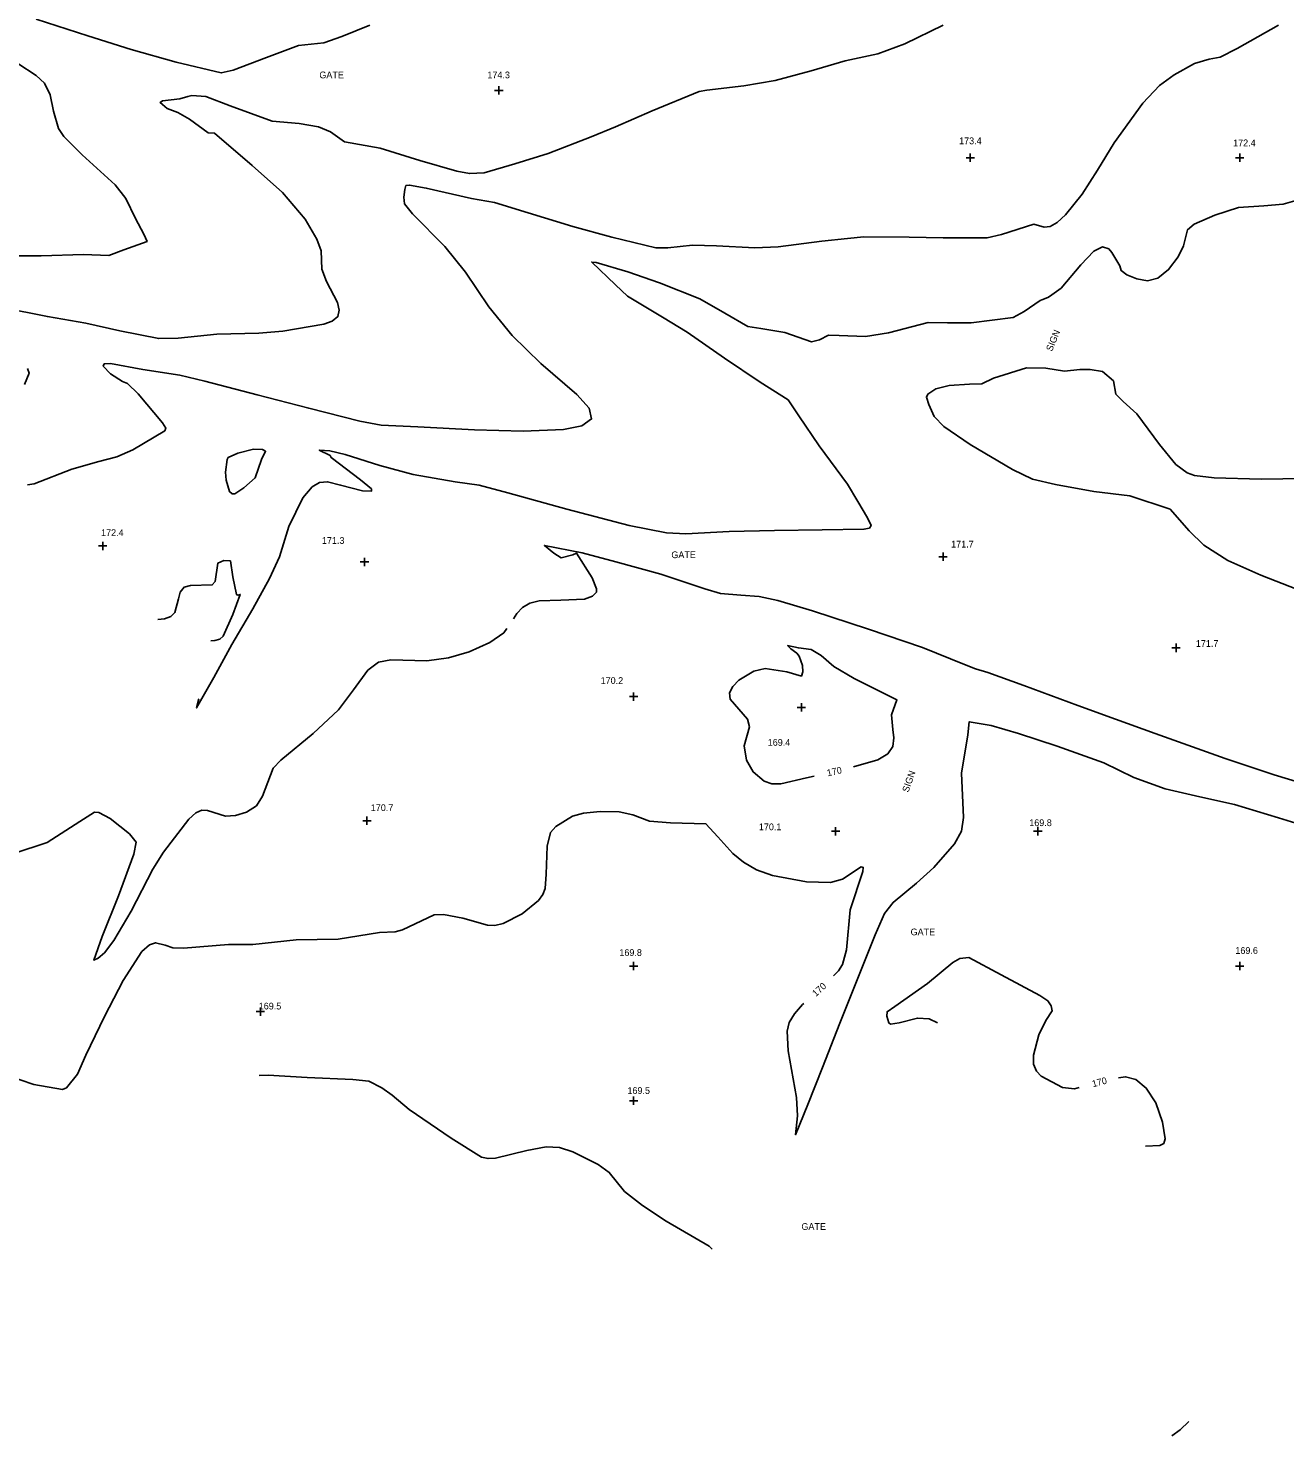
# Model space of a CAD drawing. Extents: x 1467615 to 2003689, y 770235 to 1108726.
# Drawn here: x 1997360.2 to 1997733.4, y 775740.5 to 776158.5 of the extents above; entities that cross this region are included whole.
import ezdxf

# ---------------------------------------------------------------- set-up
doc = ezdxf.new("R2010")
doc.units = 0
for name, color, linetype in [('RD_DTM_Major1', 7, 'Continuous'), ('RD_DTM_Major1_Lbl', 7, 'Continuous'), ('RD_DTM_Minor1', 7, 'Continuous'), ('RD_DTM_Spot_Elev', 7, 'Continuous'), ('RD_TX_Misc1', 7, 'Continuous')]:
    doc.layers.add(name, color=color, linetype=linetype)

msp = doc.modelspace()

# ---------------------------------------------------------------- linework, layer by layer
at = {"layer": 'RD_DTM_Major1'}
for points in [[(1997362.62, 776161.17), (1997377.91, 776156.18), (1997390.79, 776152.18), (1997404.2, 776148.39), (1997417.56, 776145.17), (1997421.12, 776145.99), (1997430.95, 776149.74), (1997440.52, 776153.37), (1997448.02, 776154.07), (1997453.38, 776156.03), (1997461.66, 776159.38)], [(1997353.3, 776090.9), (1997364.12, 776090.83), (1997376.68, 776091.32), (1997384.18, 776090.99), (1997388.61, 776092.65), (1997395.53, 776095.16), (1997394.57, 776097.26), (1997392.1, 776101.92), (1997389.19, 776107.94), (1997386.05, 776111.96), (1997376.28, 776120.86), (1997370.78, 776126.3), (1997369.26, 776128.66), (1997367.71, 776133.87), (1997366.8, 776138.72), (1997365.07, 776142.18), (1997362.63, 776144.4), (1997357.11, 776147.96)], [(1997593.58, 775936.4), (1997591.32, 775935.88), (1997583.69, 775934.06), (1997581.08, 775934.13), (1997578.83, 775934.88), (1997575.54, 775937.63), (1997573.53, 775941.12), (1997572.82, 775945.38), (1997574.42, 775951.03), (1997573.86, 775953.31), (1997568.64, 775959.22), (1997568.5, 775961.08), (1997569.47, 775963.02), (1997571.28, 775964.87), (1997575.7, 775967.6), (1997579.06, 775968.3), (1997585.51, 775967.39), (1997589.85, 775966.09), (1997590.28, 775967.34), (1997590.15, 775969.23), (1997589.22, 775972), (1997588.48, 775972.93), (1997586.68, 775974.18), (1997585.72, 775975.13), (1997588.96, 775974.48), (1997592.74, 775974), (1997595.73, 775972.18), (1997599.48, 775968.98), (1997605.46, 775965.37), (1997618.2, 775959.06), (1997616.62, 775954.58), (1997616.95, 775950.25), (1997617.26, 775947.72), (1997616.97, 775945.23), (1997615.51, 775943.02), (1997612.55, 775941.25), (1997605.26, 775939.13)], [(1997590.53, 775868.89), (1997590.2, 775868.59), (1997587.74, 775865.82), (1997586.23, 775863.2), (1997585.57, 775860.62), (1997585.91, 775854.82), (1997588.35, 775840.98), (1997588.68, 775835.52), (1997588.06, 775829.89), (1997591.7, 775838.88), (1997596.07, 775849.84), (1997601.29, 775862.99), (1997606.42, 775875.88), (1997611.77, 775889.27), (1997614.52, 775895.59), (1997617.07, 775898.9), (1997623.97, 775904.63), (1997629.15, 775909.23), (1997635.3, 775916.29), (1997637.41, 775920.02), (1997638.01, 775924.1), (1997637.35, 775937.22), (1997639.24, 775948.66), (1997639.66, 775952.55), (1997646.19, 775951.38), (1997654.31, 775949.08), (1997665.78, 775945.25), (1997679.64, 775940.34), (1997688.57, 775935.95), (1997697.88, 775932.65), (1997708.19, 775930.28), (1997718.47, 775927.95), (1997731.47, 775924.04), (1997744.41, 775920.04)], [(1997349.64, 775848.99), (1997361.89, 775844.86), (1997370.44, 775843.36), (1997371.56, 775843.85), (1997374.88, 775847.85), (1997377.33, 775853.55), (1997382.86, 775864.98), (1997388.45, 775875.71), (1997394, 775884.3), (1997396.24, 775886.31), (1997398.07, 775886.94), (1997400.87, 775886.16), (1997403.17, 775885.39), (1997406.4, 775885.33), (1997419.69, 775886.38), (1997426.92, 775886.42), (1997439.79, 775887.76), (1997452.26, 775887.97), (1997464.58, 775889.93), (1997469.18, 775890.2), (1997471.43, 775890.77), (1997480.76, 775895.23), (1997483.55, 775895.35), (1997489.34, 775894.17), (1997496.59, 775892.11), (1997498.82, 775892.07), (1997501.28, 775892.61), (1997506.96, 775895.5), (1997511.74, 775899.42), (1997513.07, 775901.25), (1997513.75, 775903.04), (1997514.03, 775907.25), (1997514.3, 775915.62), (1997515.3, 775919.64), (1997516.91, 775921.48), (1997521.84, 775924.52), (1997525.11, 775925.38), (1997530.06, 775925.87), (1997535.71, 775925.75), (1997539.77, 775924.85), (1997544.76, 775922.99), (1997550.96, 775922.48), (1997561.46, 775922.26), (1997565.05, 775918.39), (1997569.46, 775913.43), (1997572.6, 775910.83), (1997576.54, 775908.55), (1997581.3, 775906.85), (1997591.36, 775905.04), (1997598.49, 775904.8), (1997602.02, 775905.76), (1997607.56, 775909.44), (1997608.2, 775909.28), (1997608.1, 775908.12), (1997604.36, 775896.68), (1997603.25, 775884.8), (1997602.09, 775880.44), (1997600.89, 775878.57), (1997599.33, 775877.05)], [(1997672.36, 775843.94), (1997670.89, 775843.55), (1997667.41, 775843.9), (1997661.08, 775847.31), (1997659.61, 775848.78), (1997658.75, 775850.83), (1997658.72, 775853.54), (1997660.34, 775859.57), (1997662.39, 775863.79), (1997664.26, 775866.75), (1997664, 775868.19), (1997663, 775869.63), (1997660.63, 775871.3), (1997649.2, 775877.43), (1997639.6, 775882.52), (1997636.91, 775882.25), (1997634.76, 775881.02), (1997627.27, 775874.85), (1997617.55, 775868.02), (1997615.26, 775866.42), (1997615.16, 775865.1), (1997615.81, 775863.09), (1997616.31, 775862.75), (1997618.85, 775863.15), (1997624.3, 775864.55), (1997627.8, 775864.31), (1997630.28, 775863.12)], [(1997692.02, 775826.51), (1997696.3, 775826.7), (1997697.44, 775827.35), (1997697.83, 775828.69), (1997697.11, 775833.62), (1997695.04, 775839.43), (1997692.24, 775843.77), (1997689.19, 775846.28), (1997686.08, 775847.13), (1997684.01, 775846.82)]]:
    msp.add_lwpolyline(points, dxfattribs=at)
at = {"layer": 'RD_DTM_Minor1'}
for points in [[(1997352.52, 776075.58), (1997365.95, 776072.85), (1997377.37, 776070.85), (1997387.46, 776068.6), (1997399, 776066.3), (1997404.79, 776066.39), (1997416.23, 776067.66), (1997428.77, 776067.94), (1997435.82, 776068.5), (1997448.01, 776070.62), (1997450.54, 776071.48), (1997452.19, 776072.83), (1997452.62, 776074.74), (1997452.1, 776077.02), (1997448.83, 776083.24), (1997447.39, 776086.88), (1997447.2, 776092.37), (1997445.91, 776095.87), (1997442.46, 776101.79), (1997435.75, 776109.67), (1997426.7, 776117.66), (1997415.54, 776127.27), (1997413.66, 776127.42), (1997408.1, 776131.45), (1997404.63, 776133.39), (1997401.49, 776134.61), (1997399.39, 776136.37), (1997400.07, 776136.88), (1997405.23, 776137.51), (1997407.66, 776138.16), (1997408.86, 776138.44), (1997412.99, 776138.17), (1997420.18, 776135.46), (1997432.66, 776130.9), (1997440.65, 776130.13), (1997446.47, 776129.2), (1997450.05, 776127.74), (1997454.18, 776124.73), (1997464.8, 776122.8), (1997476.57, 776119.16), (1997487.53, 776116.04), (1997491.27, 776115.28), (1997495.59, 776115.49), (1997504.75, 776118.17), (1997514.66, 776121.28), (1997527.44, 776126.17), (1997534.6, 776129.22), (1997545.48, 776133.97), (1997559.47, 776139.62), (1997561.79, 776140.08), (1997572.74, 776141.34), (1997582.03, 776142.91), (1997592.72, 776145.76), (1997602.81, 776148.76), (1997612.56, 776150.88), (1997620.6, 776153.8), (1997631.89, 776159.33)], [(1997360.01, 776022.91), (1997362.01, 776023.17), (1997373.19, 776027.57), (1997381.21, 776029.76), (1997386.57, 776031.2), (1997391.28, 776033.26), (1997400.85, 776038.96), (1997401.14, 776039.74), (1997400.07, 776041.27), (1997392.9, 776049.89), (1997389.7, 776052.99), (1997388.21, 776053.53), (1997384.72, 776055.88), (1997382.51, 776058.16), (1997382.83, 776058.82), (1997384.63, 776058.87), (1997394.25, 776057.15), (1997405.22, 776055.42), (1997412.67, 776053.64), (1997428.18, 776049.65), (1997443.55, 776045.6), (1997458.74, 776041.77), (1997465.07, 776040.62), (1997475.93, 776040.06), (1997492.77, 776039.18), (1997507.19, 776038.86), (1997519.18, 776039.34), (1997524.62, 776040.4), (1997527.53, 776042.43), (1997526.78, 776045.63), (1997523.18, 776049.73), (1997512.49, 776058.95), (1997503.92, 776067.26), (1997497.05, 776075.77), (1997490.13, 776086.07), (1997484, 776093.61), (1997474.4, 776103.31), (1997472, 776106.35), (1997471.77, 776108.33), (1997472.12, 776110.55), (1997472.39, 776111.72), (1997473.51, 776111.86), (1997478.45, 776110.98), (1997491.84, 776107.91), (1997498.74, 776106.74), (1997508.73, 776103.66), (1997521.92, 776099.63), (1997533.51, 776096.37), (1997546.62, 776093.29), (1997550.18, 776093.21), (1997557.53, 776094), (1997564.58, 776093.87), (1997576.01, 776093.27), (1997582.96, 776093.51), (1997595.88, 776095.23), (1997603.48, 776096), (1997608.42, 776096.49), (1997621.86, 776096.43), (1997631.96, 776096.25), (1997644.97, 776096.24), (1997649.27, 776097.2), (1997658.84, 776100.25), (1997661.91, 776099.34), (1997663.68, 776099.63), (1997665.81, 776100.79), (1997668.26, 776103.02), (1997673.19, 776109.14), (1997677.74, 776116.28), (1997682.75, 776124.47), (1997691.25, 776136.25), (1997696.19, 776141.43), (1997700.49, 776144.64), (1997706.55, 776147.95), (1997710.93, 776149.23), (1997714.17, 776149.88), (1997719.26, 776152.39), (1997731.51, 776159.34)], [(1997663.49, 776078.84), (1997667.01, 776081.29), (1997672.78, 776088.18), (1997676.72, 776092.22), (1997679.25, 776093.51), (1997681.1, 776092.94), (1997682.06, 776091.85), (1997684.41, 776087.95), (1997684.82, 776086.5), (1997686.49, 776085.21), (1997689.42, 776084.01), (1997692.64, 776083.48), (1997695.73, 776084.22), (1997698.87, 776086.77), (1997701.69, 776090.55), (1997703.32, 776093.89), (1997704.5, 776098.64), (1997706.49, 776100.24), (1997712.65, 776102.93), (1997719.67, 776105.19), (1997727.19, 776105.73), (1997732.87, 776106.26), (1997737.09, 776107.45)], [(1997410.95, 775959.37), (1997410.26, 775956.63), (1997415.4, 775965.64), (1997420.73, 775975.5), (1997426.9, 775986.02), (1997431.85, 775995.1), (1997434.9, 776001.55), (1997437.61, 776010.51), (1997441.81, 776018.99), (1997444.54, 776022.24), (1997446.75, 776023.56), (1997449.14, 776023.78), (1997453.01, 776022.83), (1997459.51, 776021.11), (1997462.18, 776021.03), (1997462.22, 776021.65), (1997458.94, 776024.41), (1997450.18, 776030.97), (1997449.95, 776031.55), (1997446.66, 776033.2), (1997449.85, 776032.94), (1997454.4, 776031.84), (1997464.65, 776028.6), (1997474.58, 776025.93), (1997487.06, 776023.77), (1997494.11, 776022.78), (1997502.62, 776020.54), (1997520.15, 776015.68), (1997538.72, 776010.8), (1997549.81, 776008.59), (1997555.49, 776008.31), (1997568.36, 776008.99), (1997581.8, 776009.36), (1997595.96, 776009.54), (1997608.41, 776009.67), (1997610.03, 776010.06), (1997610.55, 776010.8), (1997609.46, 776013.1), (1997606.63, 776017.93), (1997603.51, 776023.06), (1997595.13, 776034.48), (1997589.05, 776043.37), (1997585.94, 776048.07), (1997577.56, 776053.32), (1997566.97, 776060.45), (1997555.87, 776068.18), (1997548.59, 776072.63), (1997538.23, 776078.9), (1997534.67, 776082.3), (1997527.6, 776089.02), (1997528.91, 776088.89), (1997538.31, 776086.09), (1997547.71, 776082.87), (1997559.69, 776078.08), (1997567.08, 776073.9), (1997573.91, 776069.88), (1997577.84, 776069.28), (1997584.87, 776068.14), (1997592.8, 776065.31), (1997595.21, 776065.94), (1997597.89, 776067.3), (1997601.03, 776067.19), (1997608.91, 776066.89), (1997615.68, 776067.99), (1997627.51, 776071.08), (1997633.19, 776071.02), (1997640.27, 776071.01), (1997652.7, 776072.6), (1997656, 776074.34), (1997660.7, 776077.62), (1997661.21, 776077.81)], [(1997661.21, 776077.81), (1997663, 776078.5), (1997663.49, 776078.84)], [(1997359.17, 776052.69), (1997360.48, 776056.05), (1997360.03, 776057.47)], [(1997737.19, 775991.81), (1997726.22, 775996.01), (1997716.49, 776000.41), (1997709.34, 776004.98), (1997704.98, 776009.26), (1997699.32, 776015.61), (1997687.37, 776019.59), (1997676.63, 776020.95), (1997665.3, 776022.94), (1997658.45, 776024.61), (1997652.54, 776027.41), (1997639.93, 776034.87), (1997632.11, 776040.2), (1997629.23, 776043.14), (1997627.66, 776046.76), (1997626.97, 776048.88), (1997627.37, 776049.84), (1997629.75, 776051.41), (1997633.68, 776052.37), (1997639.75, 776052.75), (1997643.41, 776052.86), (1997646.9, 776054.56), (1997656.64, 776057.63), (1997662.42, 776057.55), (1997667.99, 776056.62), (1997672.49, 776057.12), (1997675.54, 776057.12), (1997679.21, 776056.51), (1997682.5, 776053.73), (1997683.24, 776049.81), (1997685.41, 776047.58), (1997689.46, 776043.96), (1997696.2, 776034.88), (1997701.06, 776028.94), (1997704.38, 776026.46), (1997706.59, 776025.7), (1997712.45, 776024.98), (1997726.32, 776024.53), (1997739.25, 776024.73)], [(1997419.05, 776024.28), (1997420.04, 776020.89), (1997420.78, 776020.24), (1997421.55, 776020.23), (1997424.28, 776022), (1997427.67, 776024.98), (1997429.48, 776030.4), (1997430.72, 776032.86), (1997429.85, 776033.35), (1997427.15, 776033.49), (1997422.5, 776032.33), (1997419.59, 776030.98), (1997419.3, 776030.44), (1997418.86, 776026.64), (1997419.05, 776024.28)], [(1997504.32, 775983.07), (1997505.36, 775984.7), (1997506.99, 775986.41), (1997509.19, 775987.72), (1997512.01, 775988.41), (1997518.43, 775988.61), (1997525.43, 775988.93), (1997527.76, 775989.79), (1997528.95, 775991.06), (1997529.01, 775992.05), (1997527.72, 775995.29), (1997523.06, 776002.63), (1997522, 776002.12), (1997518.49, 776001.21), (1997516.37, 776002.63), (1997513.52, 776004.89), (1997524.78, 776002.67), (1997534.77, 776000.03), (1997548.12, 775996.35), (1997561.13, 775992.01), (1997565.84, 775990.6), (1997571.89, 775990.09), (1997577.29, 775989.69), (1997582.85, 775988.5), (1997593.18, 775985.44), (1997609.72, 775980.06), (1997625.79, 775974.56), (1997638.31, 775969.54), (1997641.58, 775968.22), (1997645.19, 775967.14), (1997655.86, 775963.31), (1997671.97, 775957.38), (1997683.11, 775953.29), (1997694.85, 775949.02), (1997715.64, 775941.66), (1997730.23, 775936.82), (1997744.03, 775932.57)], [(1997398.73, 775982.91), (1997400.67, 775983.08), (1997402.57, 775983.79), (1997403.8, 775985.02), (1997404.85, 775989.03), (1997405.4, 775991.04), (1997406.51, 775992.46), (1997408.43, 775993.01), (1997414.88, 775993.17), (1997415.73, 775994.14), (1997416.5, 775999.58), (1997418.32, 776000.41), (1997420.3, 776000.27), (1997421.01, 775995.58), (1997422.05, 775990.33), (1997422.52, 775990.14), (1997423.21, 775990.33), (1997420.97, 775984.35), (1997418.16, 775977.96), (1997417.14, 775977.06), (1997415.66, 775976.62), (1997414.47, 775976.57)], [(1997355.93, 775913.38), (1997365.87, 775916.72), (1997375.59, 775922.96), (1997379.92, 775925.7), (1997381.16, 775925.55), (1997384.58, 775923.77), (1997390.3, 775919.28), (1997392.32, 775916.78), (1997391.64, 775913.21), (1997387.04, 775900.88), (1997382.23, 775888.81), (1997379.74, 775881.7), (1997381, 775882.31), (1997382.94, 775883.97), (1997385.69, 775887.54), (1997390.8, 775896.29), (1997397.26, 775908.81), (1997400.41, 775913.83), (1997407.9, 775923.64), (1997410, 775925.48), (1997411.83, 775926.27), (1997413.43, 775926.21), (1997418.84, 775924.46), (1997421.75, 775924.71), (1997425.08, 775925.68), (1997428.02, 775927.57), (1997429.79, 775930.45), (1997432.98, 775938.73), (1997435.3, 775941.16), (1997444.81, 775949.01), (1997452.42, 775956.08), (1997456.82, 775961.98), (1997461.12, 775967.87), (1997464.26, 775970.23), (1997467.9, 775970.88), (1997478.59, 775970.66), (1997485.05, 775971.53), (1997491.15, 775973.31), (1997497.35, 775976.06), (1997501.44, 775978.98), (1997502.4, 775980.24)], [(1997428.87, 775847.49), (1997431.48, 775847.55), (1997443.05, 775846.89), (1997456.65, 775846.27), (1997461.39, 775845.84), (1997465.22, 775843.88), (1997468.28, 775841.65), (1997473.37, 775837.42), (1997485.87, 775828.86), (1997494.82, 775823.3), (1997496.78, 775822.82), (1997498.99, 775822.92), (1997508.35, 775825.26), (1997514.06, 775826.32), (1997517.98, 775826.12), (1997521.98, 775824.86), (1997529.46, 775821.09), (1997532.76, 775818.71), (1997537.32, 775813.04), (1997542.7, 775808.86), (1997549.64, 775804.29), (1997562.4, 775796.8), (1997563.36, 775795.95)], [(1997699.85, 775740.51), (1997702.28, 775742.25), (1997704.9, 775744.72)]]:
    msp.add_lwpolyline(points, dxfattribs=at)
at = {"layer": 'RD_DTM_Spot_Elev'}
for p, q in [((1997500, 776138.75), (1997500, 776141.25)), ((1997498.75, 776140), (1997501.25, 776140)), ((1997638.75, 776120), (1997641.25, 776120)), ((1997640, 776118.75), (1997640, 776121.25)), ((1997718.75, 776120), (1997721.25, 776120)), ((1997720, 776118.75), (1997720, 776121.25)), ((1997381.12, 776004.73), (1997383.62, 776004.73)), ((1997382.37, 776003.48), (1997382.37, 776005.98)), ((1997631.89, 776000.27), (1997631.89, 776002.77)), ((1997458.85, 775999.99), (1997461.35, 775999.99)), ((1997460.1, 775998.74), (1997460.1, 776001.24)), ((1997630.64, 776001.52), (1997633.14, 776001.52)), ((1997699.83, 775974.49), (1997702.33, 775974.49)), ((1997701.08, 775973.24), (1997701.08, 775975.74)), ((1997540, 775958.75), (1997540, 775961.25)), ((1997538.75, 775960), (1997541.25, 775960)), ((1997588.59, 775956.81), (1997591.09, 775956.81)), ((1997589.84, 775955.56), (1997589.84, 775958.06)), ((1997460.84, 775921.91), (1997460.84, 775924.41)), ((1997459.59, 775923.16), (1997462.09, 775923.16)), ((1997598.75, 775920), (1997601.25, 775920)), ((1997600, 775918.75), (1997600, 775921.25)), ((1997658.8, 775920.04), (1997661.3, 775920.04)), ((1997660.05, 775918.79), (1997660.05, 775921.29)), ((1997538.75, 775880), (1997541.25, 775880)), ((1997540, 775878.75), (1997540, 775881.25)), ((1997718.75, 775880), (1997721.25, 775880)), ((1997720, 775878.75), (1997720, 775881.25)), ((1997427.95, 775866.46), (1997430.45, 775866.46)), ((1997429.2, 775865.21), (1997429.2, 775867.71)), ((1997538.75, 775840), (1997541.25, 775840)), ((1997540, 775838.75), (1997540, 775841.25))]:
    msp.add_line(p, q, dxfattribs=at)

# ---------------------------------------------------------------- texts
at = {"layer": 'RD_DTM_Major1_Lbl'}
for rotation, p in [(12.9646, (1997597.65, 775936.31)), (42.0651, (1997594.13, 775870.79)), (14.9555, (1997676.43, 775843.99))]:
    msp.add_text('170', height=2, rotation=rotation, dxfattribs=at).set_placement(p)
at = {"layer": 'RD_DTM_Spot_Elev'}
for s, p in [('174.3', (1997496.59, 776143.59)), ('173.4', (1997636.67, 776124.02)), ('172.4', (1997718.04, 776123.41)), ('172.4', (1997381.88, 776007.69)), ('171.3', (1997447.45, 776005.35)), ('171.7', (1997634.3, 776004.27)), ('171.7', (1997706.97, 775974.77)), ('170.2', (1997530.22, 775963.76)), ('169.4', (1997579.84, 775945.4)), ('170.7', (1997461.96, 775926.01)), ('169.8', (1997657.5, 775921.55)), ('170.1', (1997577.21, 775920.33)), ('169.8', (1997535.78, 775883.01)), ('169.6', (1997718.7, 775883.62)), ('169.5', (1997428.69, 775867.11)), ('169.5', (1997538.18, 775842.03))]:
    msp.add_text(s, height=2, dxfattribs=at).set_placement(p)
at = {"layer": 'RD_TX_Misc1'}
for p in [(1997446.7, 776143.59), (1997551.22, 776001.11), (1997622.26, 775889.13), (1997589.84, 775801.66)]:
    msp.add_text('GATE', height=2, dxfattribs=at).set_placement(p)
for rotation, p in [(67.7824, (1997664.25, 776062.35)), (70.7505, (1997621.6, 775931.43))]:
    msp.add_text('SIGN', height=2, rotation=rotation, dxfattribs=at).set_placement(p)

doc.saveas('drawing.dxf')
